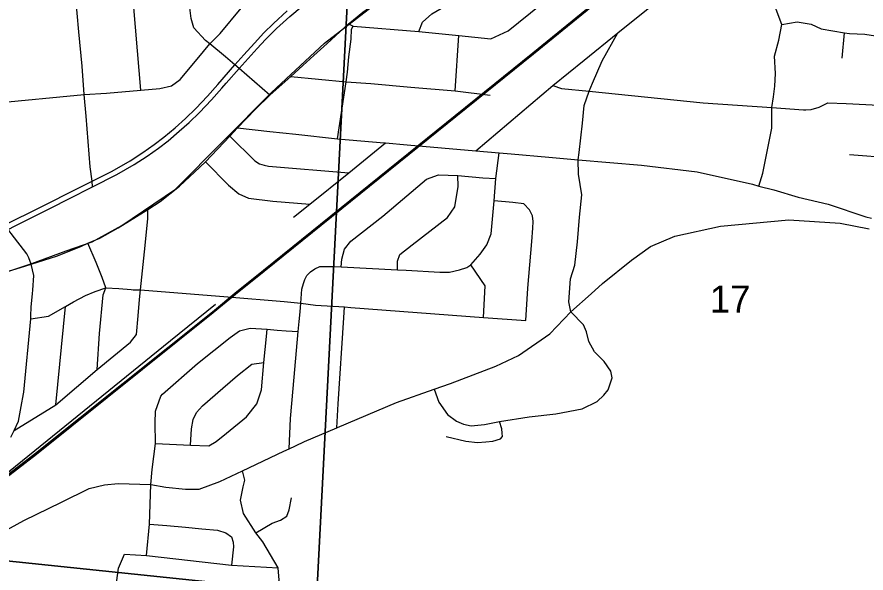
# Model space of a CAD drawing. Extents: x 0 to 34, y 0 to 22.
# Drawn here: x 18.276 to 19.579, y 18.097 to 18.951 of the extents above; entities that cross this region are included whole.
import ezdxf

# ---------------------------------------------------------------- set-up
doc = ezdxf.new("R2010")
doc.units = 0
for name, color, linetype in [('GM_X_City_Street', 7, 'Continuous'), ('GM_X_County_Road', 7, 'Continuous'), ('GM_X_Rail_Line', 7, 'Continuous'), ('GM_X_Section', 7, 'Continuous'), ('GM_X_Section_Text', 7, 'Continuous'), ('GM_X_State_Route', 7, 'Continuous'), ('GM_X_Township_Road', 7, 'Continuous')]:
    doc.layers.add(name, color=color, linetype=linetype)

msp = doc.modelspace()

# ---------------------------------------------------------------- linework, layer by layer
at = {"layer": 'GM_X_City_Street'}
for p, q in [((18.9482, 18.837), (18.954, 18.922)), ((19.5427, 18.8872), (19.5462, 18.9262)), ((18.3355, 18.3551), (18.35, 18.5064))]:
    msp.add_line(p, q, dxfattribs=at)
for points in [[(18.9803, 18.7452), (19.0985, 18.8452), (19.1463, 18.8841), (19.1979, 18.9264), (19.2909, 19.0008), (19.4167, 19.1019), (19.5201, 19.189), (19.6678, 19.3091), (19.8152, 19.4273), (19.9, 19.4966)], [(19.0031, 18.917), (19.0296, 18.9293), (19.0801, 18.9695), (19.2076, 19.0746), (19.2144, 19.0808), (19.2808, 19.1342), (19.3478, 19.188), (19.4146, 19.2426), (19.4806, 19.296), (19.5043, 19.3148), (19.5275, 19.3333), (19.5459, 19.3477), (19.5788, 19.3734), (19.6133, 19.4029), (19.6238, 19.4106), (19.6382, 19.4226), (19.6582, 19.4386), (19.6674, 19.4461), (19.6707, 19.4498), (19.674, 19.4551)], [(18.1851, 18.8141), (18.2039, 18.8156), (18.2397, 18.8183), (18.379, 18.8316), (18.413, 18.8337), (18.4658, 18.8384), (18.4949, 18.841), (18.5127, 18.8449), (18.5264, 18.8548), (18.5524, 18.8857), (18.572, 18.9092), (18.5875, 18.9251), (18.6197, 18.9639), (18.6823, 19.0374), (18.7387, 19.0696), (18.7823, 19.0947), (18.7996, 19.1059)], [(18.3918, 18.6897), (18.3909, 18.6984), (18.3878, 18.7205), (18.3819, 18.7982), (18.379, 18.8316), (18.3757, 18.875), (18.3707, 18.9278), (18.3657, 18.9855), (18.3649, 19.0102), (18.3684, 19.0296), (18.3721, 19.0395), (18.378, 19.0511), (18.3847, 19.0606), (18.3997, 19.0712), (18.4208, 19.081), (18.4451, 19.0806), (18.4636, 19.0776), (18.5344, 19.0647), (18.6017, 19.0514), (18.6823, 19.0374)], [(18.4658, 18.8384), (18.4605, 18.8984), (18.4451, 19.0806)], [(19.4145, 18.691), (19.4207, 18.7106), (19.4347, 18.7801), (19.4348, 18.8116), (19.4373, 18.8282), (19.4393, 18.8442), (19.4404, 18.8636), (19.4389, 18.8903), (19.4451, 18.9148), (19.4497, 18.9393), (19.4398, 18.9662), (19.4145, 18.992), (19.4077, 19.0078), (19.4073, 19.0201), (19.4132, 19.0381), (19.4262, 19.0546), (19.4422, 19.0713)], [(18.6638, 18.8308), (18.6168, 18.8716), (18.6103, 18.8771), (18.596, 18.8892), (18.572, 18.9092), (18.5653, 18.9145), (18.5471, 18.9339), (18.543, 18.9483), (18.5402, 18.9729), (18.5379, 19.0142), (18.5344, 19.0647)], [(18.8924, 18.9285), (18.898, 18.9428), (18.9128, 18.9552), (18.9433, 18.9732)], [(19.4497, 18.9393), (19.4734, 18.9431), (19.4949, 18.9396), (19.5103, 18.9322), (19.5462, 18.9262), (19.5538, 18.9252), (19.5774, 18.9242), (19.5937, 18.9216), (19.6209, 18.9067), (19.6343, 18.9016), (19.7086, 18.8961), (19.7732, 18.8909), (19.8383, 18.8866), (19.8423, 18.8863)], [(18.7675, 18.7637), (18.781, 18.8512), (18.7832, 18.8659), (18.7852, 18.8894), (18.7886, 18.9163), (18.7892, 18.9319), (18.7916, 18.9363)], [(18.7848, 18.94), (18.7916, 18.9363), (18.8924, 18.9285), (18.954, 18.922), (19.0031, 18.917)], [(19.1387, 18.7424), (19.1438, 18.7875), (19.1463, 18.8148), (19.1541, 18.8366), (19.159, 18.8488), (19.1742, 18.8833), (19.1979, 18.9264)], [(18.696, 18.8594), (18.781, 18.8512), (18.819, 18.8484), (18.8805, 18.843), (18.9482, 18.837), (19.0023, 18.8306)], [(19.0985, 18.8452), (19.1116, 18.8408), (19.1541, 18.8366), (19.3291, 18.8187), (19.4348, 18.8116), (19.483, 18.8078), (19.487, 18.808)], [(19.487, 18.808), (19.4949, 18.8084), (19.5071, 18.812), (19.5208, 18.8187), (19.5488, 18.8178), (19.7792, 18.806), (19.8758, 18.8002)], [(18.6144, 18.7802), (18.6639, 18.7748), (18.7037, 18.7705), (18.7675, 18.7637), (18.8393, 18.7575), (18.8416, 18.7573), (18.8746, 18.7545), (18.9803, 18.7452), (19.0162, 18.742), (19.0346, 18.7404), (19.0923, 18.7352), (19.1374, 18.7311), (19.2344, 18.723), (19.3197, 18.713), (19.4051, 18.6939), (19.4145, 18.691), (19.4379, 18.6851), (19.4749, 18.674), (19.5213, 18.663), (19.579, 18.6437), (19.5877, 18.642)], [(18.6026, 18.7675), (18.6406, 18.7298), (18.6478, 18.7251), (18.6554, 18.723), (18.662, 18.7218), (18.7849, 18.7115)], [(18.7004, 18.6432), (18.7253, 18.6633), (18.7849, 18.7115), (18.8416, 18.7573)], [(18.6936, 18.2878), (18.6957, 18.334), (18.6996, 18.3803), (18.7076, 18.4677), (18.7091, 18.483), (18.7105, 18.4979), (18.7115, 18.5111), (18.7132, 18.5328), (18.7156, 18.5416), (18.7178, 18.5478), (18.7206, 18.5537), (18.7262, 18.5594), (18.7328, 18.5638), (18.7404, 18.5675), (18.7494, 18.5674), (18.7608, 18.5677), (18.7734, 18.567), (18.8597, 18.5626), (18.8731, 18.5619), (18.9247, 18.5588), (18.9395, 18.559), (18.9552, 18.5626), (18.9661, 18.5659), (18.9723, 18.57), (18.9869, 18.5865), (18.9971, 18.601), (19.0038, 18.6177), (19.0083, 18.6683), (19.011, 18.7025), (19.0162, 18.742)], [(19.1259, 18.4981), (19.1227, 18.5134), (19.1256, 18.5485), (19.132, 18.5698), (19.136, 18.6052), (19.1395, 18.6431), (19.1427, 18.6776), (19.1378, 18.7091), (19.1374, 18.7311), (19.1387, 18.7424)], [(19.5536, 18.7396), (19.6197, 18.7344), (19.7205, 18.7259), (19.7491, 18.725), (19.7879, 18.7223), (19.8304, 18.7198), (19.8678, 18.7171), (19.9062, 18.7143), (19.9499, 18.7116), (19.9869, 18.708), (20.0137, 18.7067), (20.0305, 18.7054)], [(18.5651, 18.7283), (18.6004, 18.6926), (18.6165, 18.6791), (18.6312, 18.6722), (18.6684, 18.6678), (18.7253, 18.6633)], [(18.7734, 18.567), (18.7743, 18.579), (18.7787, 18.5942), (18.788, 18.6066), (18.8376, 18.6448), (18.9042, 18.7016), (18.9228, 18.7085), (18.9523, 18.7072), (18.991, 18.7039), (19.011, 18.7025)], [(18.8597, 18.5626), (18.8597, 18.5755), (18.8636, 18.5858), (18.8823, 18.6008), (18.9367, 18.6426), (18.9479, 18.6592), (18.953, 18.6905), (18.9523, 18.7072)], [(19.0568, 18.4847), (19.0602, 18.5342), (19.0662, 18.6057), (19.0679, 18.6265), (19.0681, 18.6368), (19.0672, 18.6454), (19.0626, 18.6546), (19.0536, 18.6637), (19.037, 18.6658), (19.0083, 18.6683)], [(18.464, 18.5169), (18.4653, 18.5316), (18.4714, 18.5903), (18.4765, 18.6407), (18.4765, 18.655)], [(18.3988, 18.4092), (18.4023, 18.4649), (18.408, 18.5239), (18.4123, 18.5347), (18.4067, 18.5507), (18.3973, 18.5736), (18.3847, 18.6034)], [(18.9921, 18.4895), (18.9944, 18.5378), (18.9723, 18.57)], [(18.2967, 18.4871), (18.3241, 18.4913), (18.35, 18.5064), (18.3622, 18.5135), (18.3807, 18.5229), (18.3956, 18.529), (18.4123, 18.5347), (18.4319, 18.5336), (18.451, 18.532), (18.4541, 18.5319)], [(18.4541, 18.5319), (18.4653, 18.5316), (18.5996, 18.521), (18.6861, 18.5139), (18.7115, 18.5111)], [(18.4497, 18.4515), (18.459, 18.4632), (18.4617, 18.492), (18.464, 18.5169)], [(18.7115, 18.5111), (18.7338, 18.5083), (18.7786, 18.5054), (18.7884, 18.5047), (18.9921, 18.4895), (19.0568, 18.4847)], [(18.7666, 18.3199), (18.769, 18.3567), (18.7774, 18.4886), (18.7786, 18.5054)], [(18.9161, 18.3792), (18.9232, 18.3592), (18.9366, 18.3401), (18.9506, 18.3301), (18.961, 18.3253), (18.9728, 18.3231), (18.9934, 18.3249), (19.0164, 18.3297), (19.0622, 18.3366), (19.1031, 18.3414), (19.1434, 18.3489), (19.1665, 18.3605), (19.1765, 18.37), (19.1833, 18.378), (19.1896, 18.3968), (19.1874, 18.4069), (19.1772, 18.4216), (19.1624, 18.4368), (19.1538, 18.4525), (19.1498, 18.4671), (19.1453, 18.4781), (19.1259, 18.4981)], [(18.4883, 18.2959), (18.5423, 18.2933), (18.5701, 18.2922), (18.5816, 18.2987), (18.5972, 18.3115), (18.6279, 18.337), (18.644, 18.3567), (18.6513, 18.3781), (18.6549, 18.4204), (18.6589, 18.4601), (18.66, 18.4711)], [(18.4964, 18.3686), (18.4991, 18.3716), (18.5528, 18.4184), (18.6028, 18.4585), (18.6174, 18.4688), (18.6336, 18.473), (18.66, 18.4711), (18.6749, 18.47), (18.689, 18.4688), (18.7076, 18.4677)], [(18.2712, 18.3159), (18.3355, 18.3551), (18.3988, 18.4092), (18.4497, 18.4515)], [(18.5423, 18.2933), (18.5435, 18.3185), (18.5461, 18.3329), (18.5512, 18.3436), (18.5603, 18.3539), (18.5919, 18.3807), (18.6141, 18.4004), (18.6361, 18.4174), (18.6549, 18.4204)], [(18.4745, 18.1241), (18.479, 18.1722), (18.4813, 18.233), (18.4834, 18.2558), (18.4883, 18.2959), (18.4877, 18.3275), (18.4881, 18.3453), (18.4964, 18.3686)], [(18.9346, 18.3064), (18.9647, 18.2992), (18.9829, 18.2972), (18.9954, 18.2983), (19.0064, 18.2995), (19.0178, 18.3031), (19.021, 18.3068), (19.0208, 18.3118), (19.0198, 18.3183), (19.0164, 18.3297)], [(18.665, 18.0436), (18.6653, 18.0457), (18.6782, 18.0861), (18.6767, 18.1051), (18.6529, 18.1447), (18.6423, 18.1587), (18.6233, 18.1883), (18.619, 18.2086), (18.6231, 18.2293), (18.6257, 18.2395), (18.622, 18.2541)], [(18.6423, 18.1587), (18.6674, 18.1737), (18.6802, 18.1783), (18.6899, 18.1843), (18.6934, 18.1942), (18.6972, 18.2125)], [(18.479, 18.1722), (18.5059, 18.17), (18.5346, 18.1673), (18.5595, 18.165), (18.5833, 18.1629), (18.5964, 18.1589), (18.605, 18.1525), (18.6078, 18.1446), (18.6081, 18.1371), (18.6049, 18.1089)], [(18.4264, 18.0668), (18.4314, 18.1047), (18.4407, 18.126)], [(18.4407, 18.126), (18.4745, 18.1241), (18.6049, 18.1089), (18.6767, 18.1051)]]:
    msp.add_lwpolyline(points, dxfattribs=at)
at = {"layer": 'GM_X_County_Road'}
msp.add_line((18.622, 18.2541), (18.6855, 18.284), dxfattribs=at)
for points in [[(18.7676, 18.3203), (18.8582, 18.359), (18.9161, 18.3792), (18.9411, 18.3879), (19.011, 18.4143), (19.0455, 18.4311), (19.0936, 18.4641), (19.1259, 18.4981), (19.1572, 18.5256), (19.1744, 18.5417), (19.2193, 18.5775), (19.2483, 18.598), (19.2858, 18.6143), (19.3556, 18.6297), (19.4609, 18.6394), (19.5393, 18.6339), (19.5842, 18.6252)], [(18.2999, 18.5313), (18.3016, 18.5538), (18.2976, 18.5712), (18.2937, 18.5811), (18.2909, 18.5869), (18.2665, 18.6182), (18.2622, 18.6244)], [(18.297, 18.492), (18.2975, 18.505), (18.2996, 18.5262), (18.2999, 18.5313)], [(18.2857, 18.3719), (18.2862, 18.3747), (18.2967, 18.4871), (18.297, 18.492)], [(18.2662, 18.3053), (18.2712, 18.3159), (18.2781, 18.3302), (18.2822, 18.3527), (18.2857, 18.3719)], [(18.6855, 18.284), (18.6936, 18.2878), (18.7034, 18.2924), (18.7169, 18.2987), (18.7666, 18.3199), (18.7676, 18.3203)], [(18.2257, 18.145), (18.2343, 18.1496), (18.2862, 18.1775), (18.3438, 18.206), (18.3867, 18.2269), (18.4098, 18.2326), (18.431, 18.2345), (18.4813, 18.233), (18.5044, 18.2286), (18.5344, 18.2258), (18.5555, 18.2258), (18.5871, 18.2373), (18.622, 18.2541)]]:
    msp.add_lwpolyline(points, dxfattribs=at)
at = {"layer": 'GM_X_Rail_Line'}
for points in [[(17.773, 17.7879), (17.7834, 17.8026), (17.8316, 17.8707), (17.8713, 17.9162), (17.9025, 17.9488), (17.9187, 17.964), (17.9435, 17.9841), (17.9632, 18.0011), (17.9952, 18.0289), (18.0752, 18.0934), (18.1653, 18.1675), (18.2466, 18.2345), (18.3055, 18.2794), (18.5769, 18.4967), (18.6112, 18.5251), (18.6554, 18.5604), (19.0687, 18.894), (19.4862, 19.2341)], [(18.2454, 18.236), (18.3043, 18.2809), (18.5757, 18.4982), (18.61, 18.5266), (18.6542, 18.5619), (19.0675, 18.8955), (19.485, 19.2356)], [(17.357, 18.2611), (17.3862, 18.2679), (17.5785, 18.3293), (17.7646, 18.394), (18.2983, 18.5724), (18.3511, 18.5914), (18.3909, 18.6055), (18.4367, 18.6303), (18.5191, 18.6864), (18.6665, 18.8349), (18.748, 18.9106), (18.8641, 19.0005)], [(18.191, 18.1941), (18.2351, 18.2304), (18.5114, 18.4541), (18.5804, 18.5095)]]:
    msp.add_lwpolyline(points, dxfattribs=at)
at = {"layer": 'GM_X_Section'}
for points in [[(17.7668, 19.1734), (18.7882, 19.078), (18.7361, 18.0659), (17.6897, 18.175)], [(18.7882, 19.078), (19.8595, 19.0129), (19.771, 17.9818), (18.7361, 18.0659)], [(17.6897, 18.175), (18.7361, 18.0659), (18.6301, 17.0536), (17.6107, 17.1586)]]:
    msp.add_lwpolyline(points, close=True, dxfattribs=at)
at = {"layer": 'GM_X_State_Route'}
for points in [[(18.6572, 18.916), (18.6592, 18.9181), (18.6742, 18.9327), (18.6947, 18.9515), (18.7136, 18.9672), (18.7311, 18.9812), (18.7558, 18.9993), (18.7825, 19.0173), (18.7883, 19.0211), (18.8338, 19.0506)], [(18.2571, 18.6316), (18.2685, 18.637), (18.3004, 18.6531), (18.3272, 18.6664), (18.3543, 18.6801), (18.3909, 18.6984), (18.4217, 18.714), (18.4492, 18.7298), (18.469, 18.7425), (18.4865, 18.7548), (18.5013, 18.7662), (18.5185, 18.7804), (18.5343, 18.7945), (18.5505, 18.81), (18.5684, 18.829), (18.584, 18.8467), (18.6103, 18.8771), (18.6242, 18.8925), (18.6401, 18.9102), (18.6548, 18.9262), (18.6697, 18.9408), (18.6903, 18.9599)], [(18.5968, 18.849), (18.6168, 18.8716), (18.6445, 18.9024), (18.6572, 18.916)], [(18.2622, 18.6244), (18.2728, 18.6299), (18.3013, 18.6444), (18.3281, 18.6577), (18.3553, 18.6714), (18.3918, 18.6897), (18.4292, 18.7086), (18.4558, 18.7242), (18.4755, 18.7369), (18.493, 18.7493), (18.5079, 18.7607), (18.5249, 18.7753), (18.5398, 18.7884), (18.556, 18.8041), (18.5745, 18.8236), (18.5902, 18.8415), (18.5968, 18.849)]]:
    msp.add_lwpolyline(points, dxfattribs=at)
at = {"layer": 'GM_X_Township_Road'}
for points in [[(18.7848, 18.94), (18.7925, 18.9464), (18.8069, 18.9578), (18.8321, 18.976), (18.8549, 18.9925), (18.8981, 19.0236), (18.9324, 19.0484), (18.9496, 19.0613), (18.9605, 19.0713), (18.9699, 19.0821), (18.9783, 19.0927), (18.9925, 19.111), (19.01, 19.1338), (19.0183, 19.1436), (19.0265, 19.153), (19.0331, 19.1597), (19.0441, 19.17), (19.06, 19.1841), (19.083, 19.2043), (19.0916, 19.2113)], [(18.696, 18.8594), (18.7143, 18.8763), (18.7316, 18.8917), (18.7517, 18.9098), (18.7648, 18.9217), (18.7848, 18.94)], [(18.3847, 18.6034), (18.403, 18.6111), (18.431, 18.627), (18.4765, 18.655), (18.4954, 18.6675), (18.5252, 18.691), (18.5483, 18.7123), (18.5651, 18.7283), (18.6026, 18.7675), (18.6144, 18.7802), (18.6418, 18.809), (18.6638, 18.8308), (18.696, 18.8594)], [(17.5633, 18.3206), (17.59, 18.3306), (17.6239, 18.3443), (17.6293, 18.3463), (17.7382, 18.3837), (17.7569, 18.3902), (17.7611, 18.3916), (17.8244, 18.4132), (17.8448, 18.4202), (17.8841, 18.4336), (17.9467, 18.4557), (18.0001, 18.4746), (18.0069, 18.477), (18.0618, 18.4964), (18.0647, 18.4973), (18.115, 18.5139), (18.1711, 18.532), (18.2153, 18.5463), (18.2811, 18.566), (18.2976, 18.5712), (18.3379, 18.5838), (18.3746, 18.5989), (18.3847, 18.6034)]]:
    msp.add_lwpolyline(points, dxfattribs=at)

# ---------------------------------------------------------------- texts
at = {"layer": 'GM_X_Section_Text'}
msp.add_text('17', height=0.04186, rotation=0, dxfattribs=at).set_placement((19.3394, 18.4965))

doc.saveas('drawing.dxf')
